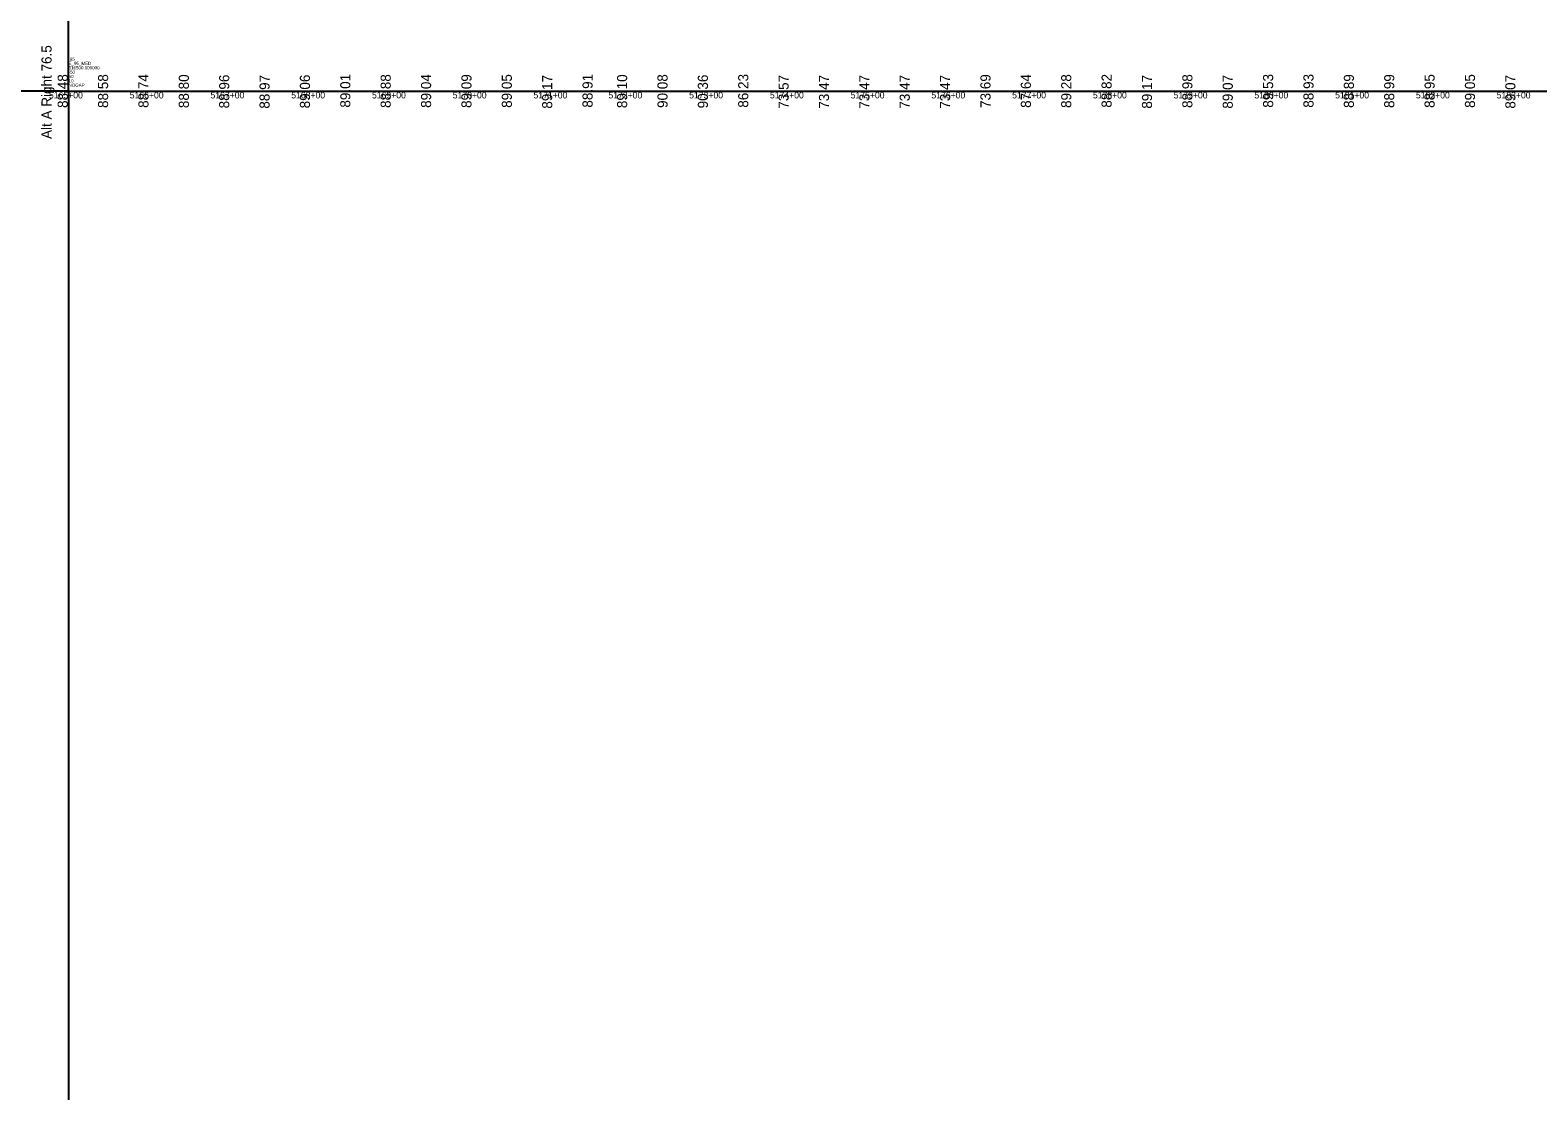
# Model space of a CAD drawing. Extents: x 2147288 to 2220488, y 740833 to 759333.
# Drawn here: x 2198841 to 2200708, y 748833 to 750159 of the extents above; entities that cross this region are included whole.
import ezdxf

# ---------------------------------------------------------------- set-up
doc = ezdxf.new("R2010")
doc.units = 0
for name, color, linetype in [('RD_DDB_Profile_EX', 7, 'Continuous'), ('RD_DDB_StaTX', 7, 'Continuous'), ('RD_GPK_Profile_Cell', 7, 'Continuous')]:
    doc.layers.add(name, color=color, linetype=linetype)

msp = doc.modelspace()

# ---------------------------------------------------------------- linework, layer by layer
at = {"layer": 'RD_GPK_Profile_Cell'}
for q in [(2198888.3, 751333.4), (2197288.3, 750083.4), (2220488.3, 750083.4), (2198888.3, 748833.4)]:
    msp.add_line((2198888.3, 750083.4), q, dxfattribs=at)

# ---------------------------------------------------------------- texts
at = {"layer": 'RD_DDB_Profile_EX'}
for s, p in [('Alt A Right 76.5', (2198867.3, 750024.2)), ('88.48', (2198887.3, 750062.6)), ('88.58', (2198937.3, 750062.6)), ('88.74', (2198987.3, 750062.7)), ('88.80', (2199037.3, 750062.4)), ('88.96', (2199087.3, 750062.1)), ('88.97', (2199137.3, 750061.7)), ('89.06', (2199187.3, 750062.1)), ('89.01', (2199237.3, 750063)), ('88.88', (2199287.3, 750062.6)), ('89.04', (2199337.3, 750062.7)), ('89.09', (2199387.3, 750062.6)), ('89.05', (2199437.3, 750062.7)), ('89.17', (2199487.3, 750061.7)), ('88.91', (2199537.3, 750063)), ('89.10', (2199580.1, 750062.4)), ('90.08', (2199630.1, 750062.6)), ('90.36', (2199680.1, 750062.1)), ('86.23', (2199730.1, 750062.9)), ('73.57', (2199780.1, 750061.7)), ('73.47', (2199830.1, 750061.7)), ('73.47', (2199880.1, 750061.7)), ('73.47', (2199930.1, 750061.7)), ('73.47', (2199980.1, 750061.7)), ('73.69', (2200030.1, 750062.6)), ('87.64', (2200080.1, 750062.7)), ('89.28', (2200130.1, 750062.6)), ('88.82', (2200180.1, 750062.9)), ('89.17', (2200230.1, 750061.7)), ('88.98', (2200280.1, 750062.6)), ('89.07', (2200330.1, 750061.7)), ('89.53', (2200380.1, 750062.9)), ('88.93', (2200430.1, 750062.9)), ('88.89', (2200480.1, 750062.6)), ('88.99', (2200530.1, 750062.6)), ('88.95', (2200580.1, 750062.7)), ('89.05', (2200630.1, 750062.7)), ('89.07', (2200680.1, 750061.7))]:
    msp.add_text(s, height=12.5, rotation=90, dxfattribs=at).set_placement(p)
at = {"layer": 'RD_DDB_StaTX'}
for s, p in [('5165+00', (2198864.1, 750074.4)), ('5165+00', (2198864.1, 750074.4)), ('5165+00', (2198864.1, 750074.4)), ('5166+00', (2198964.1, 750074.4)), ('5166+00', (2198964.1, 750074.4)), ('5166+00', (2198964.1, 750074.4)), ('5167+00', (2199064.1, 750074.4)), ('5167+00', (2199064.1, 750074.4)), ('5167+00', (2199064.1, 750074.4)), ('5168+00', (2199164.1, 750074.4)), ('5168+00', (2199164.1, 750074.4)), ('5168+00', (2199164.1, 750074.4)), ('5169+00', (2199264.1, 750074.4)), ('5169+00', (2199264.1, 750074.4)), ('5169+00', (2199264.1, 750074.4)), ('5170+00', (2199364.1, 750074.4)), ('5170+00', (2199364.1, 750074.4)), ('5170+00', (2199364.1, 750074.4)), ('5171+00', (2199464.1, 750074.4)), ('5171+00', (2199464.1, 750074.4)), ('5171+00', (2199464.1, 750074.4)), ('5172+00', (2199556.9, 750074.4)), ('5172+00', (2199556.9, 750074.4)), ('5172+00', (2199556.9, 750074.4)), ('5173+00', (2199656.9, 750074.4)), ('5173+00', (2199656.9, 750074.4)), ('5173+00', (2199656.9, 750074.4)), ('5174+00', (2199756.9, 750074.4)), ('5174+00', (2199756.9, 750074.4)), ('5174+00', (2199756.9, 750074.4)), ('5175+00', (2199856.9, 750074.4)), ('5175+00', (2199856.9, 750074.4)), ('5175+00', (2199856.9, 750074.4)), ('5176+00', (2199956.9, 750074.4)), ('5176+00', (2199956.9, 750074.4)), ('5176+00', (2199956.9, 750074.4)), ('5177+00', (2200056.9, 750074.4)), ('5177+00', (2200056.9, 750074.4)), ('5177+00', (2200056.9, 750074.4)), ('5178+00', (2200156.9, 750074.4)), ('5178+00', (2200156.9, 750074.4)), ('5178+00', (2200156.9, 750074.4)), ('5179+00', (2200256.9, 750074.4)), ('5179+00', (2200256.9, 750074.4)), ('5179+00', (2200256.9, 750074.4)), ('5180+00', (2200356.9, 750074.4)), ('5180+00', (2200356.9, 750074.4)), ('5180+00', (2200356.9, 750074.4)), ('5181+00', (2200456.9, 750074.4)), ('5181+00', (2200456.9, 750074.4)), ('5181+00', (2200456.9, 750074.4)), ('5182+00', (2200556.9, 750074.4)), ('5182+00', (2200556.9, 750074.4)), ('5182+00', (2200556.9, 750074.4)), ('5183+00', (2200656.9, 750074.4)), ('5183+00', (2200656.9, 750074.4)), ('5183+00', (2200656.9, 750074.4))]:
    msp.add_text(s, height=8, dxfattribs=at).set_placement(p)
at = {"layer": 'RD_GPK_Profile_Cell'}
for s, p in [('516500.000000', (2198888.3, 750110.4)), ('-50', (2198888.3, 750105)), ('E_95_MED', (2198888.3, 750115.8)), ('I95', (2198888.3, 750121.1)), ('50', (2198888.3, 750099.6)), ('10', (2198888.3, 750094.2)), ('NOGAP', (2198888.3, 750088.8))]:
    msp.add_text(s, height=4, dxfattribs=at).set_placement(p)

doc.saveas('drawing.dxf')
